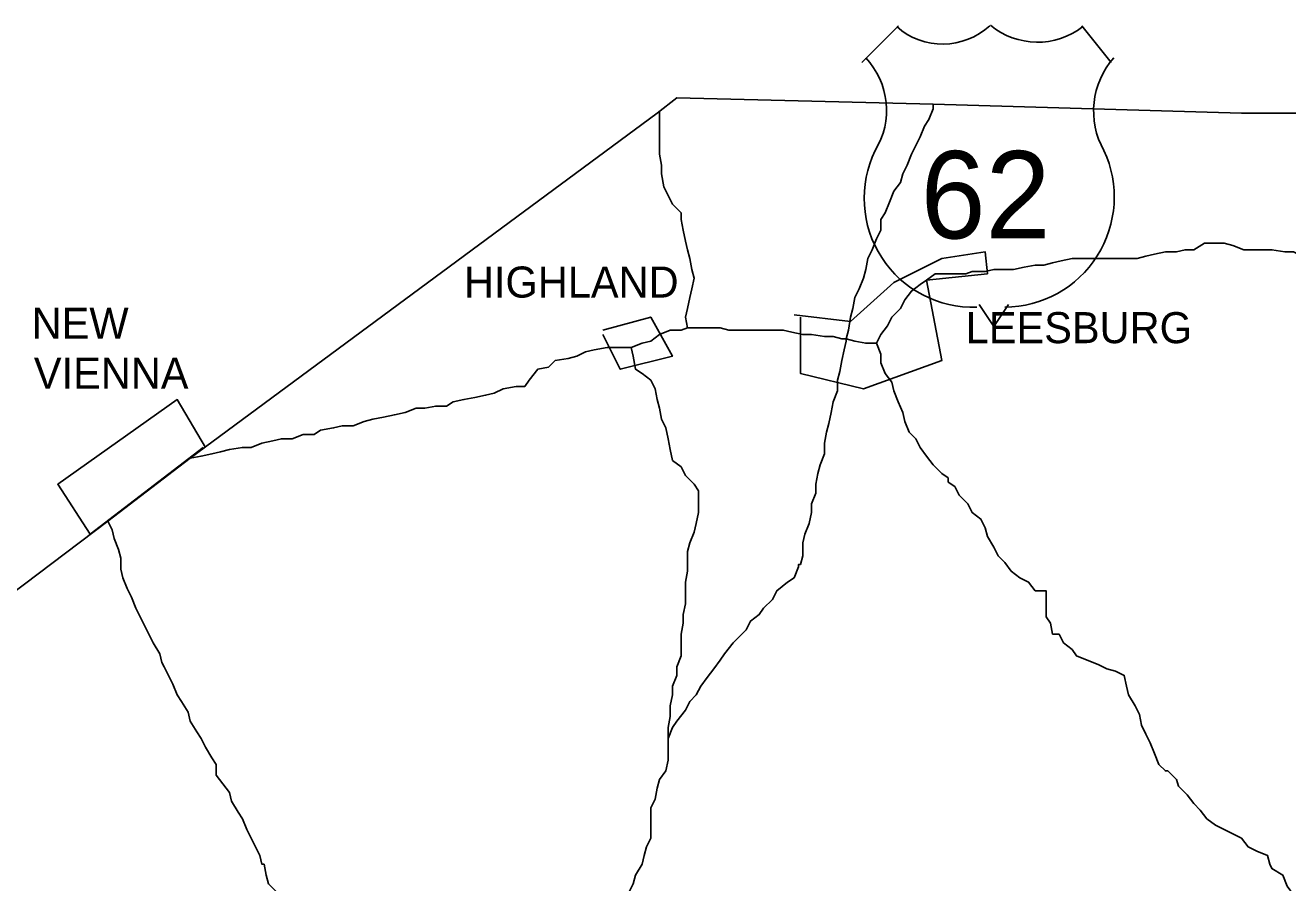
# Model space of a CAD drawing. Extents: x 0 to 34, y 0 to 22.
# Drawn here: x 3.569 to 4.361, y 18.805 to 19.343 of the extents above; entities that cross this region are included whole.
import ezdxf

# ---------------------------------------------------------------- set-up
doc = ezdxf.new("R2010")
doc.units = 0
doc.layers.add('Default', color=7, linetype='Continuous')

msp = doc.modelspace()

# ---------------------------------------------------------------- linework, layer by layer
at = {"layer": 'Default'}
for p, q in [((4.1168, 19.34291), (4.09379, 19.3199)), ((4.25025, 19.3199), (4.23184, 19.34291)), ((4.16742, 19.16805), (4.17662, 19.15425)), ((4.17662, 19.15425), (4.18583, 19.16805))]:
    msp.add_line(p, q, dxfattribs=at)
for points in [[(3.97756, 19.29775), (3.96529, 19.2882), (3.67216, 19.07142), (3.62035, 19.03188), (3.39129, 18.85872)], [(3.97756, 19.29775), (4.13845, 19.29366), (4.33205, 19.2882), (4.41522, 19.2882), (4.71654, 19.28275), (4.74381, 19.28275)], [(3.98438, 19.15322), (3.98302, 19.16004), (3.98438, 19.16549), (3.98574, 19.17231), (3.98711, 19.17776), (3.98847, 19.18458), (3.98711, 19.19004), (3.98574, 19.19685), (3.98438, 19.20231), (3.98302, 19.20776), (3.98165, 19.21458), (3.98029, 19.22139), (3.98029, 19.22548), (3.97484, 19.23094), (3.97211, 19.23639), (3.96938, 19.24185), (3.96802, 19.25003), (3.96802, 19.25548), (3.96666, 19.2623), (3.96666, 19.26775), (3.96666, 19.27457), (3.96666, 19.28138), (3.96666, 19.2882), (3.96666, 19.28957), (3.96666, 19.28957)], [(4.08391, 19.14641), (4.08527, 19.15186), (4.08664, 19.16004), (4.088, 19.16549), (4.08936, 19.17231), (4.09209, 19.17776), (4.09482, 19.18458), (4.09618, 19.19004), (4.09754, 19.19685), (4.10027, 19.20231), (4.103, 19.20912), (4.10572, 19.21458), (4.10572, 19.22139), (4.10845, 19.22548), (4.11118, 19.2323), (4.11391, 19.23912), (4.118, 19.24457), (4.11936, 19.25003), (4.12209, 19.25548), (4.12481, 19.2623), (4.12754, 19.26775), (4.13027, 19.2732), (4.13299, 19.28002), (4.13572, 19.28411), (4.13845, 19.29093), (4.13845, 19.29366)], [(4.20798, 19.19276), (4.21343, 19.19413), (4.21889, 19.19549), (4.22571, 19.19685), (4.23252, 19.19685), (4.23934, 19.19685), (4.24479, 19.19685), (4.25297, 19.19685), (4.25843, 19.19685), (4.26661, 19.19685), (4.27206, 19.19822), (4.27752, 19.19958), (4.28433, 19.20094), (4.29115, 19.20094), (4.2966, 19.20231), (4.30206, 19.20231), (4.30887, 19.2064), (4.31569, 19.2064), (4.32115, 19.2064), (4.3266, 19.20503), (4.33342, 19.20231), (4.33887, 19.20231), (4.34023, 19.20231)], [(4.34023, 19.20231), (4.34569, 19.20231), (4.35114, 19.20231), (4.35932, 19.20094), (4.36477, 19.20094), (4.37023, 19.19822), (4.37568, 19.19549), (4.3825, 19.19276), (4.38932, 19.19004), (4.39477, 19.19004), (4.40022, 19.19004), (4.40704, 19.19004), (4.41386, 19.19004), (4.41931, 19.18867), (4.42613, 19.18458), (4.43295, 19.18322), (4.43976, 19.18186), (4.44522, 19.18049), (4.45203, 19.18049), (4.45749, 19.18186), (4.45885, 19.18186)], [(4.05119, 19.1614), (4.08664, 19.15731), (4.11391, 19.18186), (4.1439, 19.19685), (4.17117, 19.20094), (4.17253, 19.18731), (4.13436, 19.18322), (4.1439, 19.13277), (4.09482, 19.11505), (4.05528, 19.12459), (4.05528, 19.16004)], [(4.103, 19.14368), (4.10572, 19.14913), (4.10981, 19.15459), (4.11254, 19.16004), (4.118, 19.16549), (4.12072, 19.17095), (4.12481, 19.1764), (4.13027, 19.18049), (4.13436, 19.18322), (4.13981, 19.18731), (4.14526, 19.18731), (4.15208, 19.18731), (4.1589, 19.18731), (4.16299, 19.18867), (4.17117, 19.18867), (4.17662, 19.19004), (4.1848, 19.19004), (4.18889, 19.19004), (4.19571, 19.1914), (4.20253, 19.19276), (4.20662, 19.19276), (4.20798, 19.19276)], [(3.93121, 19.15186), (3.9612, 19.16004), (3.97484, 19.1355), (3.94211, 19.12732), (3.93121, 19.14913)], [(3.94893, 19.14095), (3.95575, 19.14368), (3.9612, 19.14504), (3.96666, 19.14913), (3.97347, 19.15186), (3.98029, 19.15186), (3.98438, 19.15322), (3.98438, 19.15322)], [(3.94893, 19.14095), (3.95575, 19.14368), (3.9612, 19.14504), (3.96666, 19.14913), (3.97347, 19.15186), (3.98029, 19.15186), (3.98438, 19.15322), (3.98438, 19.15322)], [(3.98438, 19.15322), (3.9912, 19.15322), (3.99801, 19.15322), (4.00483, 19.15322), (4.01029, 19.15186), (4.0171, 19.15186), (4.02392, 19.15186), (4.02937, 19.15186), (4.03755, 19.15186), (4.04437, 19.15186), (4.04982, 19.1505), (4.05664, 19.14913), (4.0621, 19.14913), (4.07028, 19.14777), (4.07573, 19.14777), (4.08118, 19.14641), (4.08391, 19.14641)], [(4.05528, 19.00461), (4.05664, 19.01006), (4.05664, 19.01824), (4.058, 19.0237), (4.06073, 19.03052), (4.0621, 19.03733), (4.0621, 19.04279), (4.06482, 19.0496), (4.06482, 19.05506), (4.06619, 19.06187), (4.06755, 19.06733), (4.07028, 19.07414), (4.07028, 19.08096), (4.07164, 19.08778), (4.073, 19.09323), (4.07437, 19.10005), (4.07573, 19.10687), (4.07846, 19.11368), (4.07846, 19.1205), (4.07982, 19.12595), (4.08118, 19.13277), (4.08255, 19.13959), (4.08391, 19.14504), (4.08391, 19.14641)], [(4.08391, 19.14641), (4.08936, 19.14504), (4.09618, 19.14368), (4.103, 19.14368)], [(3.7935, 19.09732), (3.80032, 19.09869), (3.80714, 19.10005), (3.81395, 19.10278), (3.81941, 19.10278), (3.82622, 19.10414), (3.83304, 19.10414), (3.83713, 19.10687), (3.84395, 19.10823), (3.85076, 19.10959), (3.85758, 19.11096), (3.86304, 19.11232), (3.86849, 19.11505), (3.87667, 19.11641), (3.88212, 19.11641), (3.88485, 19.1205), (3.8903, 19.12732), (3.89712, 19.12868), (3.90121, 19.13277), (3.90939, 19.13414), (3.91485, 19.1355), (3.9203, 19.13823), (3.92575, 19.13959), (3.93393, 19.14095), (3.93802, 19.14095), (3.9462, 19.14095), (3.94893, 19.14095), (3.94893, 19.14095)], [(3.9912, 19.05097), (3.98847, 19.05506), (3.98302, 19.06051), (3.98029, 19.06596), (3.97484, 19.07005), (3.97347, 19.07687), (3.97211, 19.08369), (3.97075, 19.09051), (3.96802, 19.09596), (3.96666, 19.10278), (3.96529, 19.10823), (3.96393, 19.11505), (3.9612, 19.1205), (3.95575, 19.12459), (3.95166, 19.12732), (3.95029, 19.1355), (3.94893, 19.14095), (3.94893, 19.14095)], [(4.14799, 19.05915), (4.1439, 19.06187), (4.13845, 19.06733), (4.13436, 19.07278), (4.13027, 19.07824), (4.12754, 19.08369), (4.12345, 19.08778), (4.12072, 19.0946), (4.11936, 19.10005), (4.11663, 19.10687), (4.11391, 19.11368), (4.11254, 19.11914), (4.10845, 19.12459), (4.10572, 19.13141), (4.10572, 19.13686), (4.103, 19.14368), (4.103, 19.14368)], [(3.68034, 19.07824), (3.60944, 19.0237), (3.58899, 19.05506), (3.66398, 19.10823), (3.6817, 19.07824)], [(3.67216, 19.07142), (3.67897, 19.07278), (3.68579, 19.07414), (3.69124, 19.07551), (3.6967, 19.07687), (3.70488, 19.07824), (3.71033, 19.07824), (3.71715, 19.08096), (3.72397, 19.08233), (3.72942, 19.08369), (3.73624, 19.08369), (3.74305, 19.08642), (3.74987, 19.08642), (3.75396, 19.08914), (3.76214, 19.09051), (3.7676, 19.09187), (3.77441, 19.09187), (3.78123, 19.0946), (3.78668, 19.09596), (3.7935, 19.09732), (3.7935, 19.09732)], [(4.21343, 18.96098), (4.21207, 18.9678), (4.20934, 18.97189), (4.20934, 18.97734), (4.20934, 18.98143), (4.20934, 18.98825), (4.20253, 18.98825), (4.19844, 18.9937), (4.19298, 18.99643), (4.18753, 19.00052), (4.18344, 19.00597), (4.17935, 19.01006), (4.17662, 19.01552), (4.17253, 19.02233), (4.17117, 19.02779), (4.16844, 19.03324), (4.16299, 19.03733), (4.16026, 19.04279), (4.15481, 19.04824), (4.15208, 19.05369), (4.14799, 19.05642), (4.14799, 19.05915)], [(3.97211, 18.89554), (3.97211, 18.90235), (3.97347, 18.90917), (3.97347, 18.91599), (3.97484, 18.92281), (3.97484, 18.92826), (3.97756, 18.93508), (3.97756, 18.94053), (3.98029, 18.94735), (3.98029, 18.95553), (3.98029, 18.96098), (3.98165, 18.9678), (3.98165, 18.97325), (3.98302, 18.98007), (3.98302, 18.98689), (3.98302, 18.9937), (3.98438, 19.00052), (3.98438, 19.00597), (3.98438, 19.01279), (3.98574, 19.01824), (3.98847, 19.02506), (3.98983, 19.03052), (3.9912, 19.03733), (3.9912, 19.04415), (3.9912, 19.0496), (3.9912, 19.05097)], [(3.62035, 19.03188), (3.62307, 19.02643), (3.62444, 19.02097), (3.62716, 19.01415), (3.62853, 19.0087), (3.62853, 19.00188), (3.62989, 18.99643), (3.63262, 18.98961), (3.63534, 18.98416), (3.63807, 18.97734), (3.6408, 18.97189), (3.64352, 18.96643), (3.64625, 18.96098), (3.64898, 18.95553), (3.65307, 18.94871), (3.65443, 18.94326), (3.6558, 18.94053)], [(3.97211, 18.89554), (3.97484, 18.90235), (3.97756, 18.90644), (3.98302, 18.91326), (3.98574, 18.91871), (3.98983, 18.92281), (3.99256, 18.92826), (3.99665, 18.93371), (4.00074, 18.93917), (4.00483, 18.94462), (4.00756, 18.94871), (4.01301, 18.95553), (4.01574, 18.95825), (4.02119, 18.96371), (4.02392, 18.96916), (4.02937, 18.97325), (4.0321, 18.97734), (4.03755, 18.9828), (4.04028, 18.98825), (4.0471, 18.9937), (4.05119, 18.99643), (4.05391, 19.00325), (4.05391, 19.00461), (4.05528, 19.00461)], [(4.28433, 18.87509), (4.28024, 18.87918), (4.27752, 18.88599), (4.27479, 18.89281), (4.27206, 18.89826), (4.26934, 18.90372), (4.26797, 18.91053), (4.26524, 18.91599), (4.26115, 18.92281), (4.25979, 18.92826), (4.25843, 18.93508), (4.25297, 18.9378), (4.24752, 18.93917), (4.24207, 18.94189), (4.23525, 18.94462), (4.22843, 18.94735), (4.22571, 18.95144), (4.22025, 18.95553), (4.21753, 18.96098), (4.21343, 18.96098)], [(3.6558, 18.94053), (3.65852, 18.93508), (3.66125, 18.92962), (3.66398, 18.92281), (3.6667, 18.91871), (3.67079, 18.9119), (3.67216, 18.90644), (3.67625, 18.89963), (3.67897, 18.89554), (3.6817, 18.89008), (3.68579, 18.88327), (3.68852, 18.87918), (3.68852, 18.87236), (3.69261, 18.8669), (3.6967, 18.86145), (3.69806, 18.856), (3.70215, 18.84918), (3.70488, 18.84509), (3.70761, 18.83827), (3.71033, 18.83282), (3.71306, 18.82737), (3.71579, 18.82191), (3.71715, 18.81646), (3.71851, 18.81646)], [(3.94757, 18.79192), (3.94757, 18.79873), (3.95029, 18.80419), (3.95166, 18.80964), (3.95575, 18.81646), (3.95711, 18.82191), (3.95848, 18.82737), (3.9612, 18.83282), (3.9612, 18.841), (3.9612, 18.84645), (3.9612, 18.85191), (3.96393, 18.85736), (3.96529, 18.86418), (3.96666, 18.86963), (3.97075, 18.87509), (3.97211, 18.8819), (3.97211, 18.88872), (3.97211, 18.89554), (3.97211, 18.89554)], [(4.3675, 18.79192), (4.36477, 18.79737), (4.36068, 18.80282), (4.35796, 18.80964), (4.35114, 18.81373), (4.34978, 18.81646), (4.34841, 18.82191), (4.3416, 18.82464), (4.33614, 18.82737), (4.33205, 18.83282), (4.3266, 18.83555), (4.32115, 18.83827), (4.31569, 18.841), (4.31024, 18.84509), (4.30615, 18.85054), (4.30206, 18.85463), (4.29797, 18.86009), (4.29251, 18.86554), (4.29115, 18.86963), (4.2857, 18.87509), (4.28433, 18.87509), (4.28433, 18.87509)], [(3.71851, 18.81646), (3.71988, 18.80964), (3.72124, 18.80419), (3.72669, 18.79873), (3.72806, 18.79192), (3.72942, 18.78646), (3.72942, 18.78101), (3.72942, 18.77556), (3.72942, 18.76874), (3.72942, 18.76192), (3.73078, 18.75647), (3.73215, 18.75101), (3.73487, 18.7442), (3.73624, 18.73874), (3.7376, 18.73465), (3.7376, 18.73465)]]:
    msp.add_lwpolyline(points, dxfattribs=at)
for centre, radius, start, end in [((4.14455, 19.3754), 0.04388, 228.71859, 312.45521), ((4.20402, 19.37912), 0.04643, 230.45249, 307.79333), ((4.06094, 19.28989), 0.04829, 328.44295, 43.21082), ((4.28975, 19.28939), 0.05055, 138.39443, 209.34239), ((4.1636, 19.23469), 0.06842, 154.0604, 271.92319), ((4.18304, 19.23541), 0.06913, 270.37171, 24.99189)]:
    msp.add_arc(centre, radius, start, end, dxfattribs=at)

# ---------------------------------------------------------------- texts
for s, height, p in [('62', 0.05486, (4.13061, 19.20946)), ('HIGHLAND', 0.019502, (3.84395, 19.17231)), ('NEW', 0.019502, (3.57263, 19.14641)), ('LEESBURG', 0.019502, (4.1589, 19.14368)), ('VIENNA', 0.019502, (3.57399, 19.11505))]:
    msp.add_text(s, height=height, dxfattribs=at).set_placement(p)

doc.saveas('drawing.dxf')
